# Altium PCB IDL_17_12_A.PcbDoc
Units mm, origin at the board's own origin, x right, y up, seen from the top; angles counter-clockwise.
Board outline 37.71 x 41.61 mm, 6 copper layers (Top Layer - SIG1, Layer 2 - PWR, Layer 3 - SIG2, Layer 4 - SIG3, Layer 5 - GND, Bottom Layer - SIG4), stack 1.26 mm thick; 0 components, 113 nets, 0 pads, 0 vias.
Unrouted connection lines stored in the file: 39.
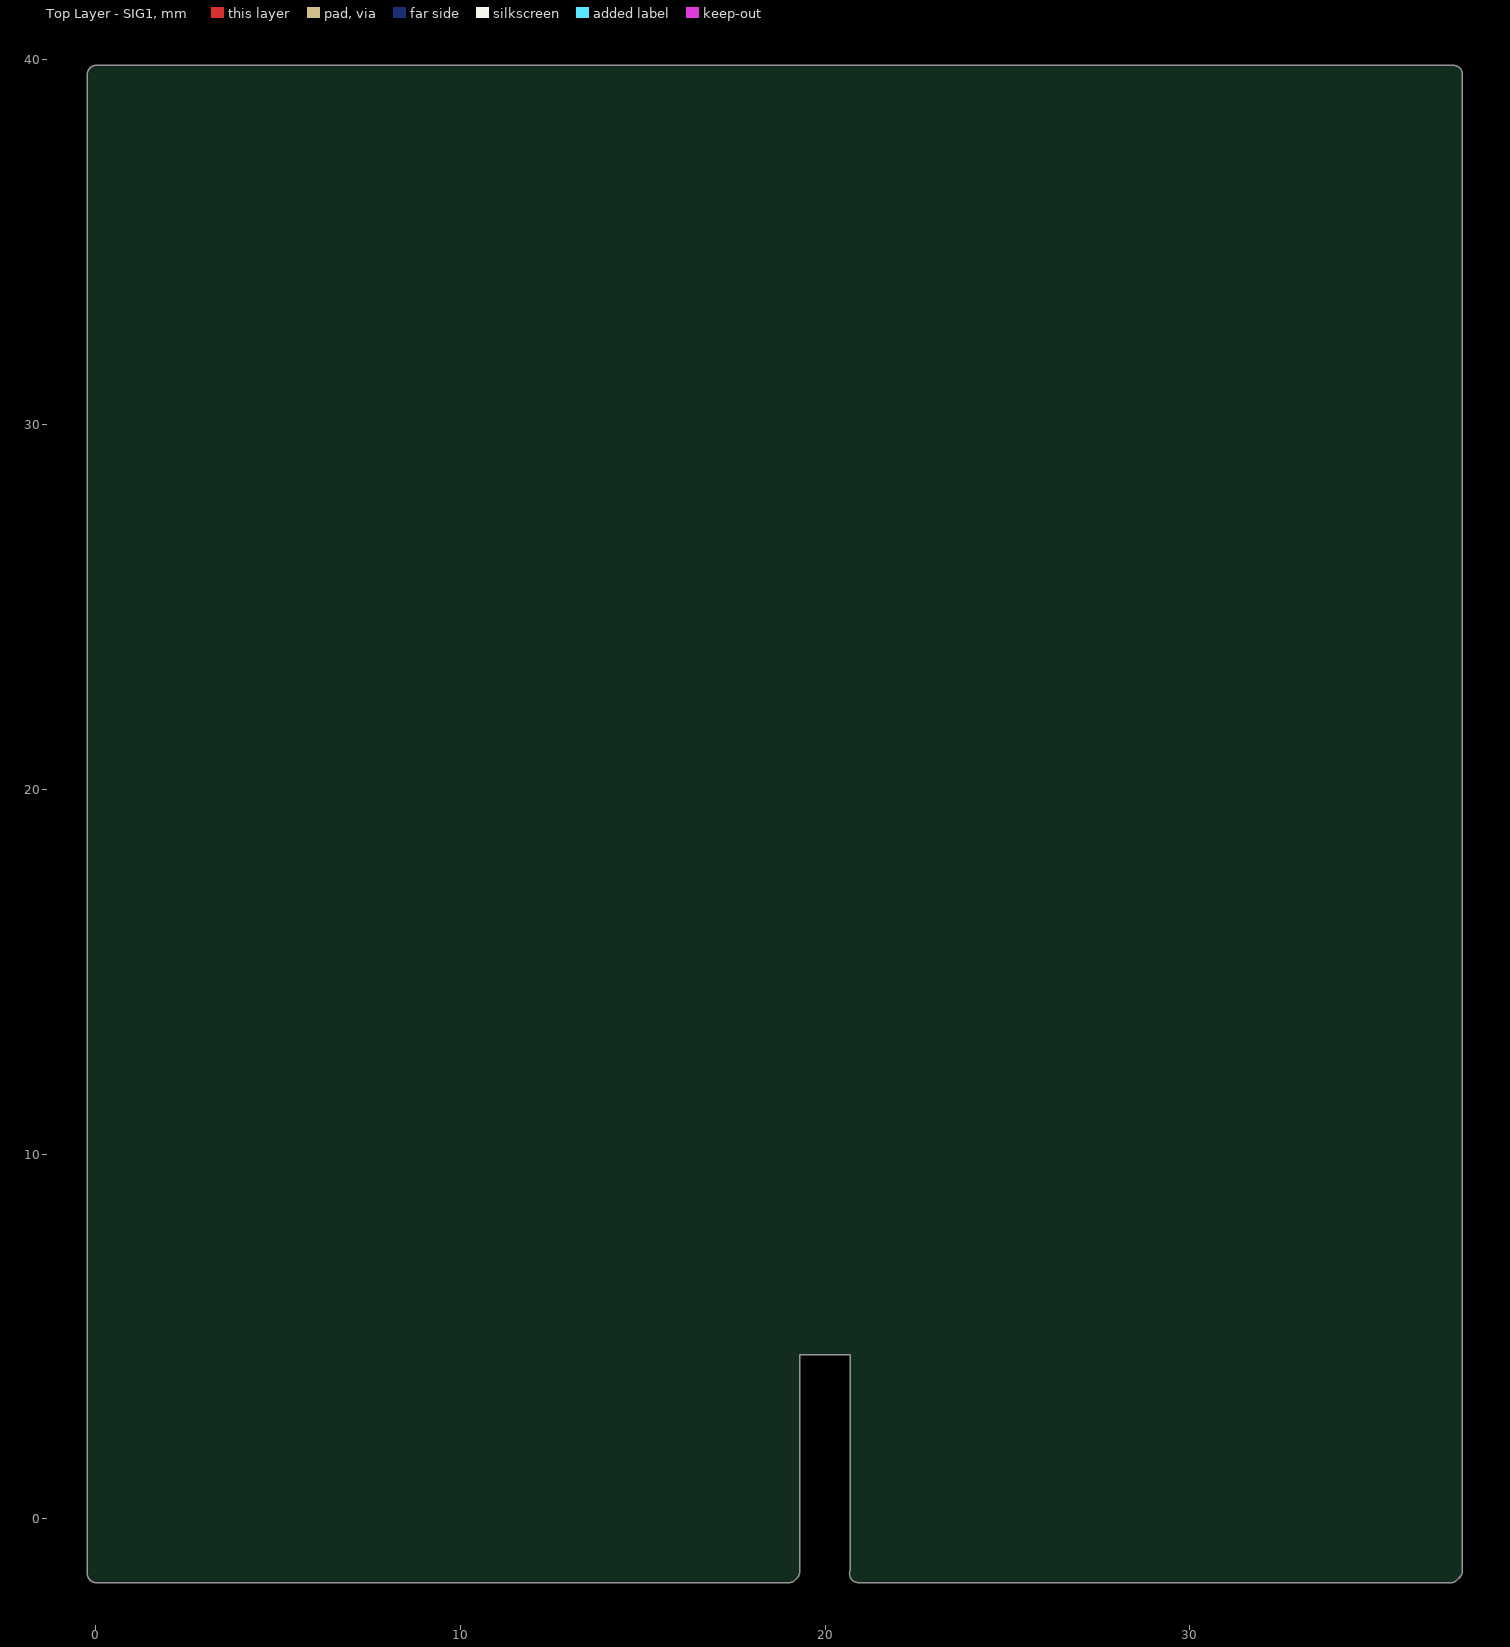
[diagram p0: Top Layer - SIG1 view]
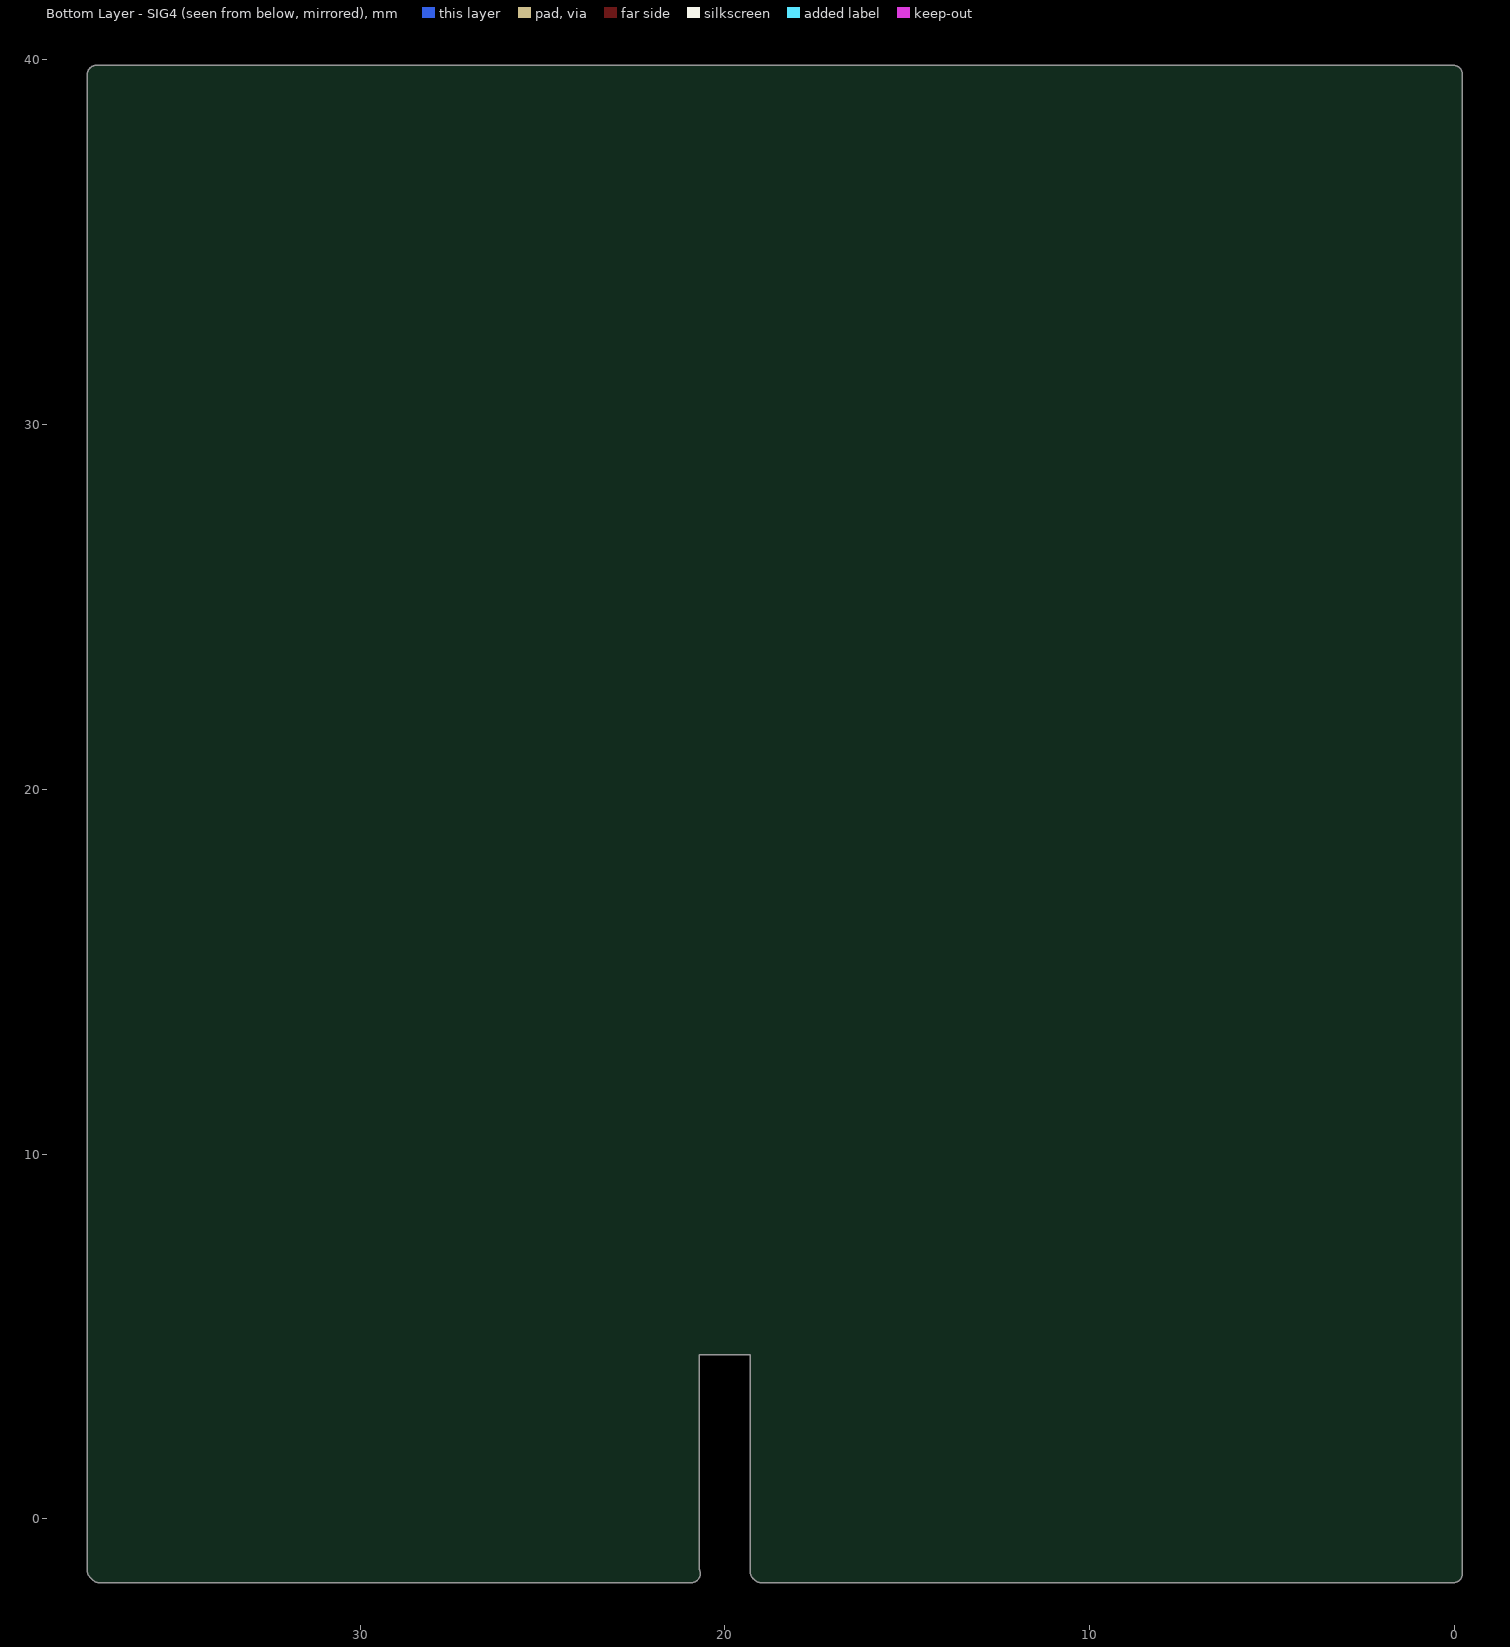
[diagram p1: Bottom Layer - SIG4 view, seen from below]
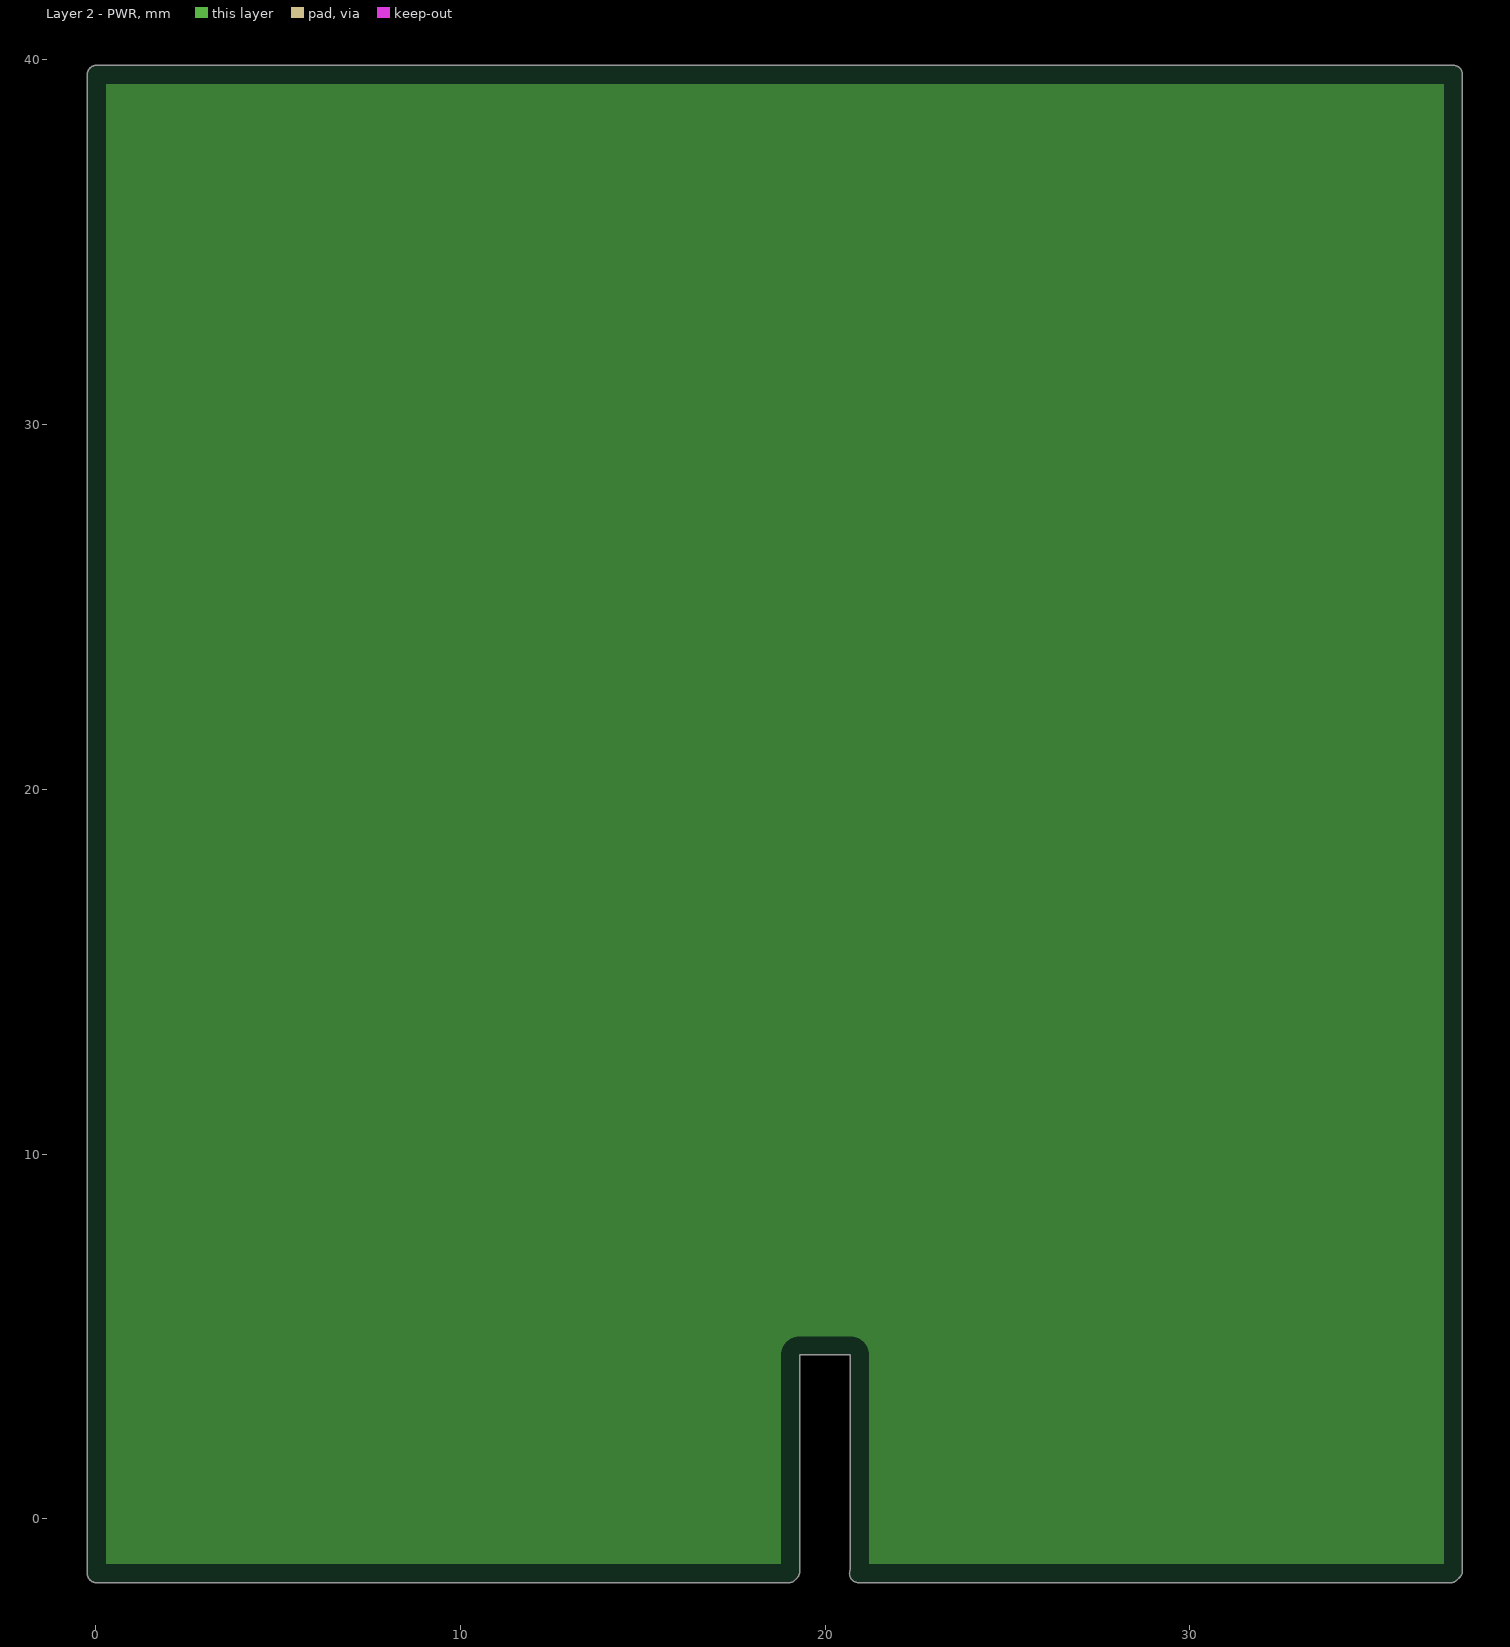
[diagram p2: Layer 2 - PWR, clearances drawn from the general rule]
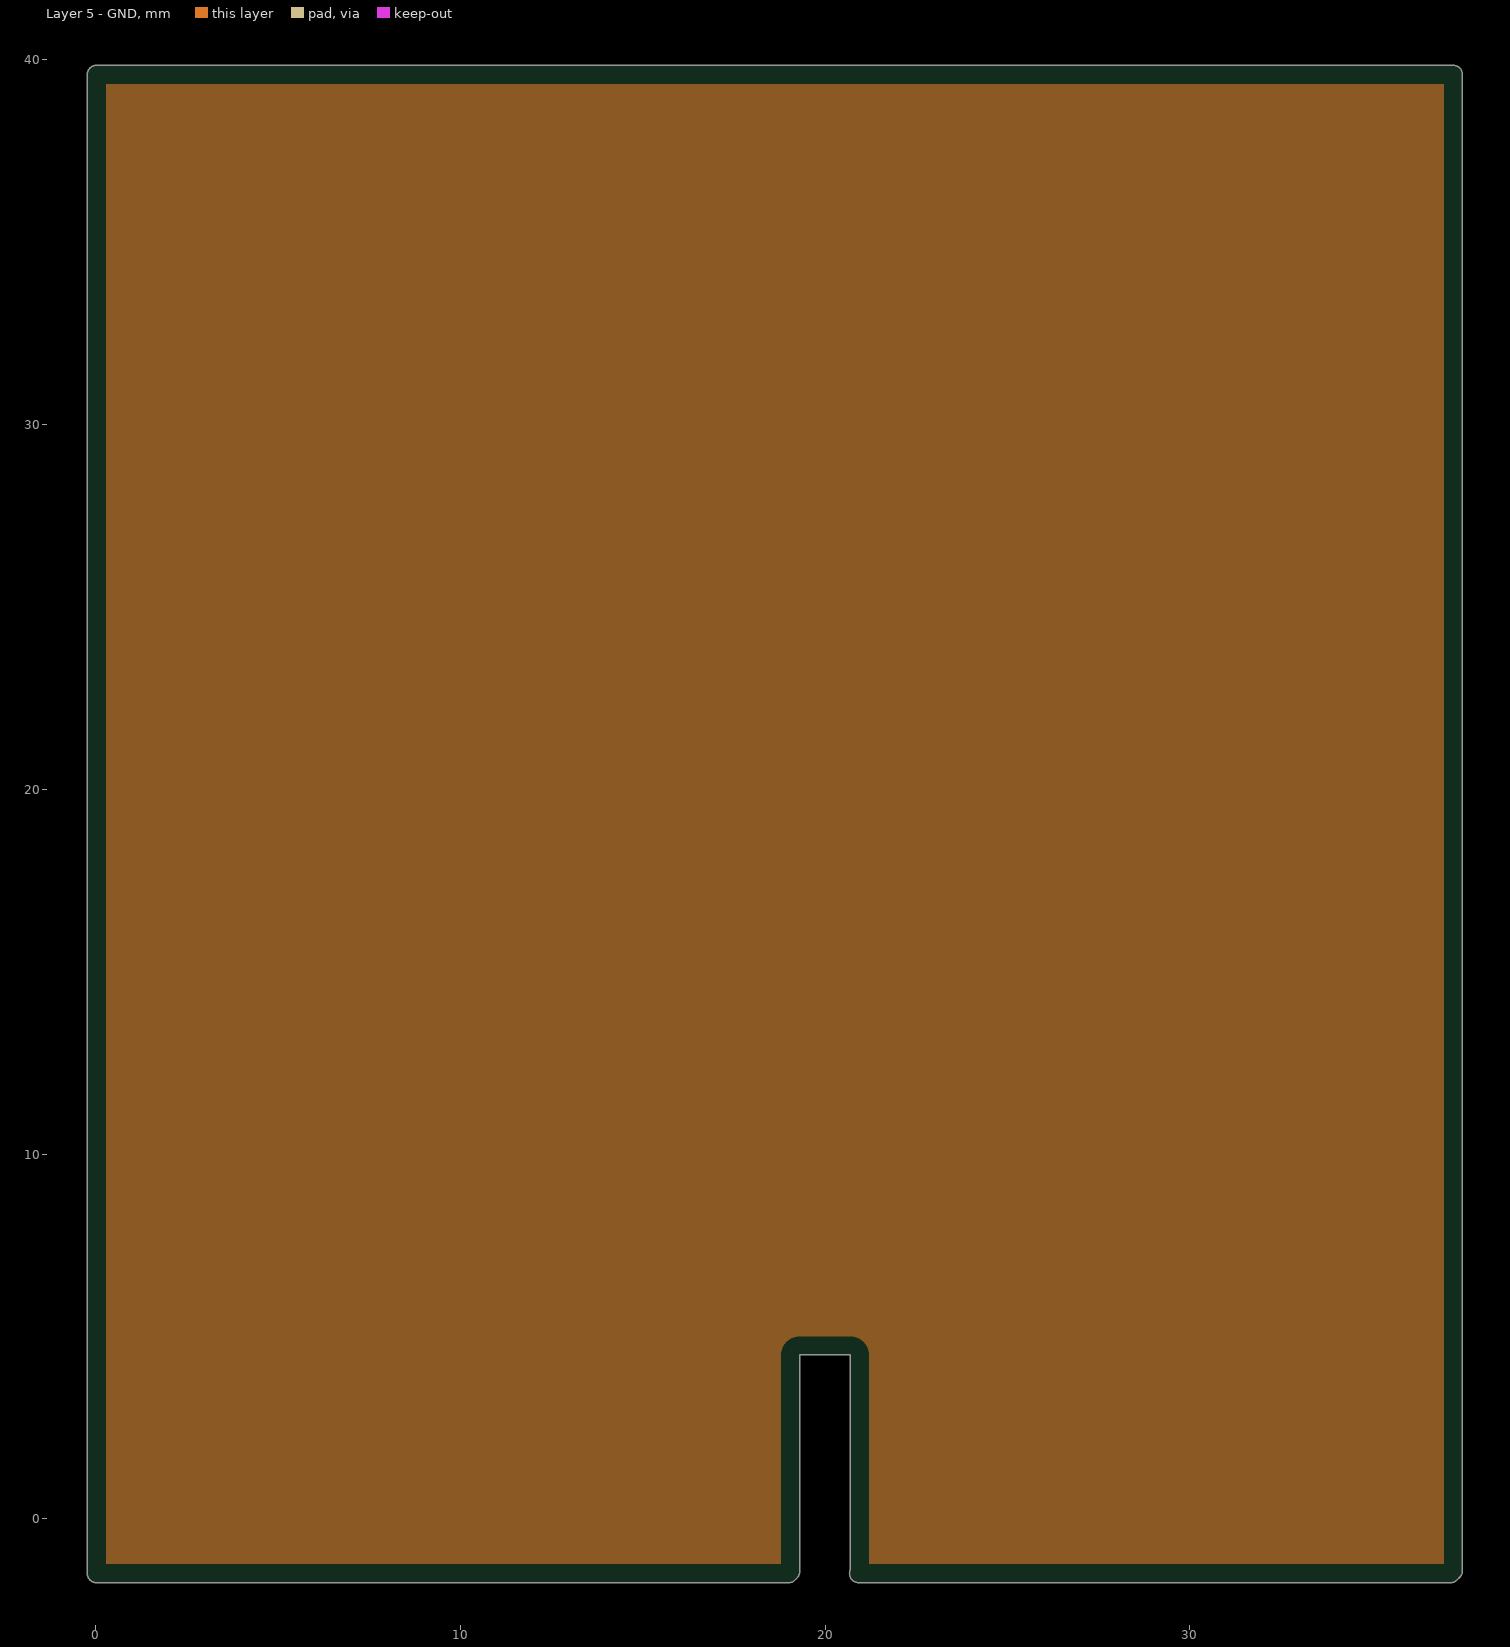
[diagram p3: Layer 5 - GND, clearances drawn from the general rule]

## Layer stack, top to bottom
Top Solder: solder mask 0.0102, Solder Resist, Dk 3.5
Top Layer - SIG1: signal copper 0.035
Dielectric 1: prepreg 0.2032, FR-4, Dk 4.65
Layer 2 - PWR: plane copper 0.018
Dielectric 3: core 0.254, FR-4, Dk 4.65
Layer 3 - SIG2: signal copper 0.018
Dielectric 6: prepreg 0.2032, FR-4, Dk 4.65
Layer 4 - SIG3: signal copper 0.018
Dielectric 5: core 0.254, FR-4, Dk 4.65
Layer 5 - GND: plane copper 0.018
Dielectric 4: prepreg 0.2032, FR-4, Dk 4.65
Bottom Layer - SIG4: signal copper 0.035
Bottom Solder: solder mask 0.0102, Solder Resist, Dk 3.5

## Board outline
0.025,-1.754 19,-1.754 ccw(c19,-1.5) 19.18,-1.68 19.23,-1.63 ccw(c19.05,-1.45) 19.304,-1.45 19.304,4.496 20.696,4.496 20.696,-1.39 ccw(c20.925,-1.5) 20.925,-1.754 37.15,-1.754 ccw(c37.15,-1.5) 37.33,-1.68 37.405,-1.605 ccw(c37.225,-1.425) 37.479,-1.425 37.479,39.6 ccw(c37.225,39.6) 37.225,39.854 0.025,39.854 ccw(c0.025,39.6) -0.229,39.6 -0.229,-1.5 ccw(c0.025,-1.5)

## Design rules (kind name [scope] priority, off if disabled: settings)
Clearance Clearance_Diff [InAnyDifferentialPair  or InNetClass('INPUT') vs InNamedPolygon('L4_5VAN') or InNamedPolygon('L3_5VAP') or InNamedPolygon('L1_GND') OR InNamedPolygon('L6_GND')   or InNamedPolygon('L3_GND') or InNamedPolygon('L4_GND')] p1: gap=0.381 ignorepadtopadclearanceinfootprint=FALSE except(0: Arc-Hole Track-Hole SMDPad-Hole THPad-Hole Via-Hole Fill-Hole Poly-Hole Region-Hole Text-Hole)
Clearance Clearance_RF [InNetClass('RF') or InNet('HV_BIAS') or InNet('NetCN1_235') vs InNamedPolygon('L4_5VAN') or InNamedPolygon('L3_5VAP') or InNamedPolygon('L1_GND') OR InNamedPolygon('L6_GND')   or InNamedPolygon('L3_GND') or InNamedPolygon('L4_GND')] p2: gap=0.508 ignorepadtopadclearanceinfootprint=FALSE except(0: Arc-Hole Track-Hole SMDPad-Hole THPad-Hole Via-Hole Fill-Hole Poly-Hole Region-Hole Text-Hole)
Clearance Clearance_Poly [InNamedPolygon('L4_5VAN') or InNamedPolygon('L3_5VAP')  or InNamedPolygon('L1_GND')     OR InNamedPolygon('L6_GND')  or InNamedPolygon('L3_GND') or InNamedPolygon('L4_GND')] p3: gap=0.203 ignorepadtopadclearanceinfootprint=FALSE except(0: Arc-Hole Track-Hole SMDPad-Hole THPad-Hole Via-Hole Fill-Hole Poly-Hole Region-Hole Text-Hole)
Clearance Clearance_KeepOut [Iskeepout] p4 off: gap=0.508 ignorepadtopadclearanceinfootprint=FALSE except(0: Arc-Hole Track-Hole SMDPad-Hole THPad-Hole Via-Hole Fill-Hole Poly-Hole Region-Hole Text-Hole)
Clearance [All] p5: gap=0.152 ignorepadtopadclearanceinfootprint=FALSE except(0: Arc-Hole Track-Hole SMDPad-Hole THPad-Hole Via-Hole Fill-Hole Poly-Hole Region-Hole Text-Hole)
ComponentClearance [All] p1 off: gap=0.254 collisioncheckmode=3 verticalgap=0.254 showdistances=FALSE
DiffPairsRouting [All] p1: maxlimit=0.254 minlimit=0.102 mostfreqgap=0.152 toplayer_minwidth=0.102 toplayer_maxwidth=0.305 toplayer_prefwidth=0.203 midlayer1_minwidth=0.102 midlayer1_maxwidth=0.305 midlayer1_prefwidth=0.203 midlayer2_minwidth=0.102 midlayer2_maxwidth=0.305 midlayer2_prefwidth=0.203 bottomlayer_minwidth=0.102 bottomlayer_maxwidth=0.305 bottomlayer_prefwidth=0.203 maxuncoupledlength=12.7
Height [All] p1 off: minheight=0 maxheight=25.4 prefheight=12.7
HoleSize [All] p1: absolutevalues=TRUE maxlimit=3.3 minlimit=0.3 maxpercent=80.000 minpercent=20.000
MinimumSolderMaskSliver [All] p1: minsoldermaskwidth=0.127
NetAntennae [All] p1 off: netantennaetolerance=0
PlaneClearance [All] p1: clearance=0.254
PlaneConnect PlaneConnect_vIA [ISvIA] p1: planeconnectstyle=Direct reliefexpansion=0.508 reliefentries=4 reliefconductorwidth=0.254 reliefairgap=0.254
PlaneConnect [All] p2: planeconnectstyle=Direct reliefexpansion=0.305 reliefentries=4 reliefconductorwidth=0.381 reliefairgap=0.203
PolygonConnect PolygonConnect_Via [IsVia or HasFootprint('ChipFET1206-8') or HasFootprint('MAXB2MPCBV') or HasFootprint('MAXB5MPCBV') or HasFootprint('MAXB6MPCBV') or HasFootprint('PINHDR2X20H') or Hasfootprint('PINHDR2X13H')  or HasFootprint('CC1210-X2Y') or HasFootprint('L-COMMCHOKE-4') or HasFootprint('CTC-D7343-43')] p1: connectstyle=Direct reliefconductorwidth=0.254 reliefentries=4 polygonreliefangle="90 Angle" airgapwidth=0.254
PolygonConnect PolygonConnect_Main [All] p2: connectstyle=Relief reliefconductorwidth=0.305 reliefentries=4 polygonreliefangle="90 Angle" airgapwidth=0.254
RoutingVias [All] p1: holewidth=0.3 width=0.65 viastyle="Through Hole" minholewidth=0.3 minwidth=0.65 maxholewidth=1 maxwidth=1.5
SilkToSilkClearance [All] p1: silktosilkclearance=0.127
SilkToSolderMaskClearance SilkscreenOverComponentPads [IsPad] p1: minsilkscreentomaskgap=0.127 clearancetoexposedcopper=TRUE
SolderMaskExpansion [All] p1: expansion=0.051
Width Width_Logo [HasFootprint('ITECH_LOGO')] p1: maxlimit=0.254 minlimit=0.025 preferedwidth=0.051
Width [All] p2: maxlimit=3.81 minlimit=0.1 preferedwidth=0.254 toplayer_prefwidth=0.203 midlayer1_prefwidth=0.203 bottomlayer_prefwidth=0.203 minimp=50.000000 maximp=50.000000 favimp=50.000000
20 further rules are at their usual default settings.

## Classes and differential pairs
net class DO_[1..16]: DO_1 DO_2 DO_3 DO_4 DO_5 DO_6 DO_7 DO_8 DO_9 DO_10 DO_11 DO_12 DO_13 DO_14 DO_15 DO_16
differential pair SSTIN: +SSTIN_P -SSTIN_N
differential pair WL_CLK: +WL_CLK_P -WL_CLK_N

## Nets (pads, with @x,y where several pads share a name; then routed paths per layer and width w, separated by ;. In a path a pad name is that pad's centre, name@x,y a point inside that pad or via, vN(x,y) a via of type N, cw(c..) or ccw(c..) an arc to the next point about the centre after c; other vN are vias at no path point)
2.5V: 
CLR: 
DO_1: 
DO_2: 
DO_3: 
DO_4: 
DO_5: 
DO_6: 
DO_7: 
DO_8: 
DO_9: 
DO_10: 
DO_11: 
DO_12: 
DO_13: 
DO_14: 
DO_15: 
DO_16: 
GND: 
ISEL: 
NetDONE1_1: 
NetDONE2_1: 
NetMON_Timing1_1: 
NetMON_Timing2_1: 
NetR1_2: 
NetR2_2: 
NetR3_2: 
NetR4_2: 
NetU5_1: 
NetU6_1: 
OROUT2_1: 
OROUT2_2: 
PCLK: 
RAMP: 
RAMPMON: 
RD_CS_S0: 
RD_RS_S0: 
RD_RS_S1: 
RD_RS_S2: 
REGCLR: 
RFIN_1_1: 
RFIN_1_2: 
RFIN_2_1: 
RFIN_2_2: 
RFIN_3_1: 
RFIN_3_2: 
RFIN_4_1: 
RFIN_4_2: 
RFIN_5_1: 
RFIN_5_2: 
RFIN_6_1: 
RFIN_6_2: 
RFIN_7_1: 
RFIN_7_2: 
RFIN_8_1: 
RFIN_8_2: 
RFIN_9_1: 
RFIN_9_2: 
RFIN_10_1: 
RFIN_10_2: 
RFIN_11_1: 
RFIN_11_2: 
RFIN_12_1: 
RFIN_12_2: 
RFIN_13_1: 
RFIN_13_2: 
RFIN_14_1: 
RFIN_14_2: 
RFIN_15_1: 
RFIN_15_2: 
RFIN_16_1: 
RFIN_16_2: 
SCLK: 
SHOUT1: 
SHOUT2: 
SHOUT_2: 
SIN_1: 
SMPLSEL_S1/RD_CS_S1: 
SMPLSEL_S2/RD_CS_S2: 
SMPLSEL_S3/RD_CS_S3: 
SMPLSEL_S4/RD_CS_S4: 
SMPLSEL_S5/RD_CS_S5: 
SMPLSL_ANY1: 
SMPLSL_ANY2: 
SR_CLOCK: 
SR_SEL: 
SSTIN_N: 
SSTIN_P: 
TRG_1_1: 
TRG_1_2: 
TRG_2_1: 
TRG_2_2: 
TRG_3_1: 
TRG_3_2: 
TRG_4_1: 
TRG_4_2: 
TRG_5_1: 
TRG_5_2: 
TRG_16_1: 
TRG_16_2: 
VADJN: 
VADJP: 
VDD1: 
VDD2: 
VDISCHARGE: 
VIN1: 
VIN2: 
VPED: 
VRAMPREF: 
WL_CLK_N: 
WL_CLK_P: 
WR_ADDRCLR: 
WR_ENA: 

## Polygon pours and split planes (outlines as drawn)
no net on Layer 2 - PWR (split plane): 36.969,-1.244 21.206,-1.244 21.206,4.496 21.196,4.595 21.167,4.691 21.12,4.779 21.057,4.857 20.979,4.92 20.891,4.967 20.795,4.996 20.696,5.006 19.304,5.006 19.205,4.996 19.109,4.967 19.021,4.92 18.943,4.857 18.88,4.779 18.833,4.691 18.804,4.595 18.794,4.496 18.794,-1.244 0.281,-1.244 0.281,39.344 36.969,39.344
no net on Layer 5 - GND (split plane): 36.969,-1.244 21.206,-1.244 21.206,4.496 21.196,4.595 21.167,4.691 21.12,4.779 21.057,4.857 20.979,4.92 20.891,4.967 20.795,4.996 20.696,5.006 19.304,5.006 19.205,4.996 19.109,4.967 19.021,4.92 18.943,4.857 18.88,4.779 18.833,4.691 18.804,4.595 18.794,4.496 18.794,-1.244 0.281,-1.244 0.281,39.344 36.969,39.344

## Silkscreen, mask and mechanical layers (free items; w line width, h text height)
Board Outline:
  lines w0.508: 0.025,-1.5 0.025,39.6 37.225,39.6 37.225,-1.425 37.15,-1.5 21.2,-1.5 20.925,-1.5 20.95,-1.475 20.95,4.675 20.875,4.75 19.05,4.75 19.05,-1.45 19,-1.5 0.025,-1.5
Sheet Top:
  lines w0.099: -68.924,-152.784 332.394,-152.784 332.394,138.806 -68.924,138.806 -68.924,-152.784 ; -66.377,-150.251 329.847,-150.251 329.847,136.273 -66.377,136.273 -66.377,-150.251
  lines w0.1: 159.93,-150.251 159.93,-132.212 329.847,-132.212 ; 159.93,-141.337 329.856,-141.337 ; 159.93,-138.308 282.358,-138.308 ; 159.93,-135.26 282.358,-135.26 ; 198.157,-141.337 198.157,-132.212 ; 223.557,-141.337 223.557,-132.212 ; 263.943,-141.337 263.943,-132.212 ; 282.358,-150.251 282.358,-132.212 ; 282.358,-136.784 329.847,-136.784
  text "Designer:" at 160.565,-134.498 h2.54
  text "Kevin Kam" at 174.916,-134.625 h2.54
  text "Revision:" at 198.792,-134.625 h2.54
  text ".Version" at 213.016,-134.625 h2.54
  text "File:" at 224.192,-134.625 h2.54
  text ".Pcb_File_Name_No_Path" at 229.272,-134.625 h2.54
  text "Sheet  1 of  1" at 264.705,-134.625 h2.54
  text "Code:" at 282.993,-135.768 h2.54
  text "Drawn By:" at 160.565,-137.546 h2.54
  text "Kevin Kam" at 174.916,-137.546 h2.54
  text "Modif. Date:" at 198.792,-137.673 h2.54
  text "Date" at 211.619,-137.673 h2.54
  text "Variant:" at 224.192,-137.673 h2.54
  text ".VariantName" at 233.463,-137.673 h2.54
  text "ID:" at 283.12,-140.34 h2.54
  text "Approved By:" at 160.565,-140.594 h2.54
  text ".Approved_By" at 174.916,-140.594 h2.54
  text "Print Date:" at 198.792,-140.721 h2.54
  text ".Print_Date" at 211.619,-140.721 h2.54
  text "Signature:" at 224.192,-140.721 h2.54
  text "Size:  A3 H" at 264.705,-140.721 h2.54
  text "Title:" at 160.565,-143.896 h2.54
  text "University of Hawaii at Manoa" at 283.156,-144.106 h2.54
  text "High Energy Physics Group" at 283.156,-146.606 h2.54
  text ".Printout_Name" at 166.28,-147.452 h4.06
  text "Instrumentation Development Laboratory" at 283.156,-149.206 h2.54
Sheet Bot:
  lines w0.099: -68.931,-152.779 -68.931,138.811 332.387,138.811 332.387,-152.779 -68.931,-152.779 ; -66.384,-150.246 -66.384,136.278 329.84,136.278 329.84,-150.246 -66.384,-150.246
  lines w0.1: -66.393,-141.332 103.533,-141.332 ; -66.384,-136.779 -18.895,-136.779 ; -66.384,-132.207 103.533,-132.207 103.533,-150.246 ; -18.895,-150.246 -18.895,-132.207 ; -18.895,-138.303 103.533,-138.303 ; -18.895,-135.255 103.533,-135.255 ; -0.48,-141.332 -0.48,-132.207 ; 39.906,-141.332 39.906,-132.207 ; 65.306,-141.332 65.306,-132.207
  text "Designer:" at 102.898,-134.493 h2.54
  text "Sheet  1 of  1" at -1.242,-134.62 h2.54
  text ".Pcb_File_Name_No_Path" at 34.191,-134.62 h2.54
  text "File:" at 39.271,-134.62 h2.54
  text ".Version" at 50.447,-134.62 h2.54
  text "Revision:" at 64.671,-134.62 h2.54
  text ".Designer" at 88.547,-134.62 h2.54
  text "Code:" at -19.53,-135.763 h2.54
  text ".Drawn_By" at 88.547,-137.541 h2.54
  text "Drawn By:" at 102.898,-137.541 h2.54
  text ".VariantName" at 30,-137.668 h2.54
  text "Variant:" at 39.271,-137.668 h2.54
  text "Date" at 51.844,-137.668 h2.54
  text "Modif. Date:" at 64.671,-137.668 h2.54
  text "ID:" at -19.657,-140.335 h2.54
  text ".Approved_By" at 88.547,-140.589 h2.54
  text "Approved By:" at 102.898,-140.589 h2.54
  text "Size:  A3 H" at -1.242,-140.716 h2.54
  text "Signature:" at 39.271,-140.716 h2.54
  text ".Print_Date" at 51.844,-140.716 h2.54
  text "Print Date:" at 64.671,-140.716 h2.54
  text "Title:" at 102.898,-143.891 h2.54
  text "University of Hawaii at Manoa" at -19.742,-144.206 h2.54
  text "High Energy Physics Group" at -19.742,-146.706 h2.54
  text ".Printout_Name" at 97.183,-147.447 h4.06
  text "Instrumentation Development Laboratory" at -19.742,-149.306 h2.54
FabNTop:
  text ".IDLnum" at 290.613,-135.768 h4.06
  text "ASSEMBLY" at 264.706,-137.706 h2.54
  text ".BoardName" at 290.613,-140.34 h4.06
FabNBot:
  text ".IDLnum" at -27.15,-135.763 h4.06
  text "ASSEMBLY" at -1.244,-137.706 h2.54
  text ".BoardName" at -27.15,-140.335 h4.06
PCBNTop:
  text ".IDLnum" at 290.613,-135.768 h4.06
  text "PCB" at 264.706,-137.706 h2.54
  text ".BoardName" at 290.613,-140.34 h4.06
PCBNBot:
  text ".IDLnum" at -27.144,-135.756 h4.06
  text "PCB" at -1.244,-137.706 h2.54
  text ".BoardName" at -27.15,-140.335 h4.06
Drill Drawing:
  text "Notes:" at 181.093,104.08 h3.3
  text "1. Board shall be fabricated - performace class II as per IPC-6011 and IPC6012" at 181.093,100.905 h2.54
  text "2. PCB manufacturer logo, P/N, revision and/or date code of manufacturing" at 181.093,97.73 h2.54
  text "shall be printed in top solder mask (not over pcb traces, allowed over copper plane)." at 183.633,95.19 h2.54
  text "The date code shall be in the format: \"WWYY\" where WW=week and YY= year, max height 0.15 inches" at 183.633,92.65 h2.54
  text "3. Silkscreen not printed on both sides" at 181.093,89.475 h2.54
  text "4. Material: high temperature FR4 class epoxy glass rated UL94V-0. UL symbol and rating shall be marked farside" at 181.093,86.3 h2.54
  text "35um copper for external layers and 18um for all internal layers" at 183.634,83.76 h2.54
  text "Must be RoHS compliant and survive a lead-free assembly max reflow of 260 deg C (5 passes)" at 183.633,81.22 h2.54
  text "Td rating: >340 deg C" at 184.903,78.045 h2.54
  text "Tg = 150 deg C (min)" at 185.006,75.244 h2.54
  text "5. Solder mask: SMOBC per IPC-SM-840C, class T must be Rohs compliant, 0.001\" max measured over bare copper plating," at 181.093,69.155 h2.54
  text "must clear all lands as indicated on gerber solder mask layers, color= GREEN" at 183.633,66.615 h2.54
  text "6. Finish: electro-less nickel immersion gold (ENIG), 0.05-0.125um Au over 3-6um Ni - over bare copper only" at 181.088,62.708 h2.54
  text "7. Solderability test: Category 2 of J-STD-003" at 181.093,58.995 h2.54
  text "8. Finished boards shall not have nicks, scratches, voids, exposed copper, poor plating or misdrilled holes" at 181.093,55.185 h2.54
  text "9. All holes sizes are after plating" at 181.093,51.375 h2.54
  text "10. PCB manufacturer may add copper thieving as needed to improve manufacturability," at 179.823,47.565 h2.54
  text "thieving to be 0.030\" round pads at 0.050\" spacing." at 183.633,45.025 h2.54
  text "Thieving will have a minimum of 0.100\" clearance from existing copper and should not be placed under surface mounted devices" at 183.633,42.485 h2.54
  text "11. PCB manufacturer may use tear drops to improve annular rings as long as DRC rules are followed" at 179.95,38.929 h2.54
  text "12. All via connections to power and ground planes are solid" at 179.95,35.373 h2.54
  text "13. All unconnected pads on inner signal layers are removed" at 179.95,31.817 h2.54
  text "14. All finished boards are to be 100% electrically tested" at 179.951,28.261 h2.54
  text "15. Unless otherwise indicated, all linear toleracnes shall be XX.X +/-0.2mm and XX.XX +/- 0.1mm" at 179.95,24.705 h2.54
  text "16. Gerber file GM1 shows board outline (milling line)" at 179.95,21.148 h2.54
  text "17. Table 1 shows Layer stack details" at 179.95,17.592 h2.54
  text "Additional notes:" at 180.077,10.862 h3.3
  text "A1. Finished board thickness = 1.27mm +/- 0.1mm; measured over top/bottom copper and solder mask" at 180.078,7.306 h2.54
  text "Table 1a: Layer Stack Details for IDL_14_35 Rev.B (Imperial Units)" at 179.656,-12.006 h2.5
  text "Table 2: NC Drill Details for IDL_14_35 Rev.B" at 179.656,-74.006 h2.5

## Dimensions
19.304,4.496 to 20.696,4.496 on Dimensions

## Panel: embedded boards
"IDL_14_35_A.PcbDoc" at -16.444,8.694, 1 rows x 1 columns, spacing 0 x 0, rotation 0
